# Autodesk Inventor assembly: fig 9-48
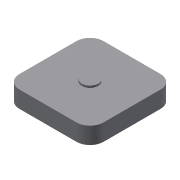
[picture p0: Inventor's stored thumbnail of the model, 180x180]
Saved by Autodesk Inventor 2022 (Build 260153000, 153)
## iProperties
Created: 2013-07
Part Number: fig 9-48
Document SubType Name: Assembly
Designer: CADCIM
Author: CADCIM
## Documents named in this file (3)
- D:\PROJECTS_2021\Resources\Part Files\c09_Inv_2022_prt\fig 9-49.iam
- D:\PROJECTS_2021\Resources\Part Files\c09_Inv_2022_prt\17 (1).ipt
- D:\PROJECTS_2021\Resources\Part Files\c09_Inv_2022_prt\18.ipt
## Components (2 placed, 2 different names)
1. 17 (1):1 — Planar:1
2. 18:1 — Planar:1
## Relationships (1: PlanarJoint 1)
- Planar:1: 17 (1):1 ↔ 18:1
